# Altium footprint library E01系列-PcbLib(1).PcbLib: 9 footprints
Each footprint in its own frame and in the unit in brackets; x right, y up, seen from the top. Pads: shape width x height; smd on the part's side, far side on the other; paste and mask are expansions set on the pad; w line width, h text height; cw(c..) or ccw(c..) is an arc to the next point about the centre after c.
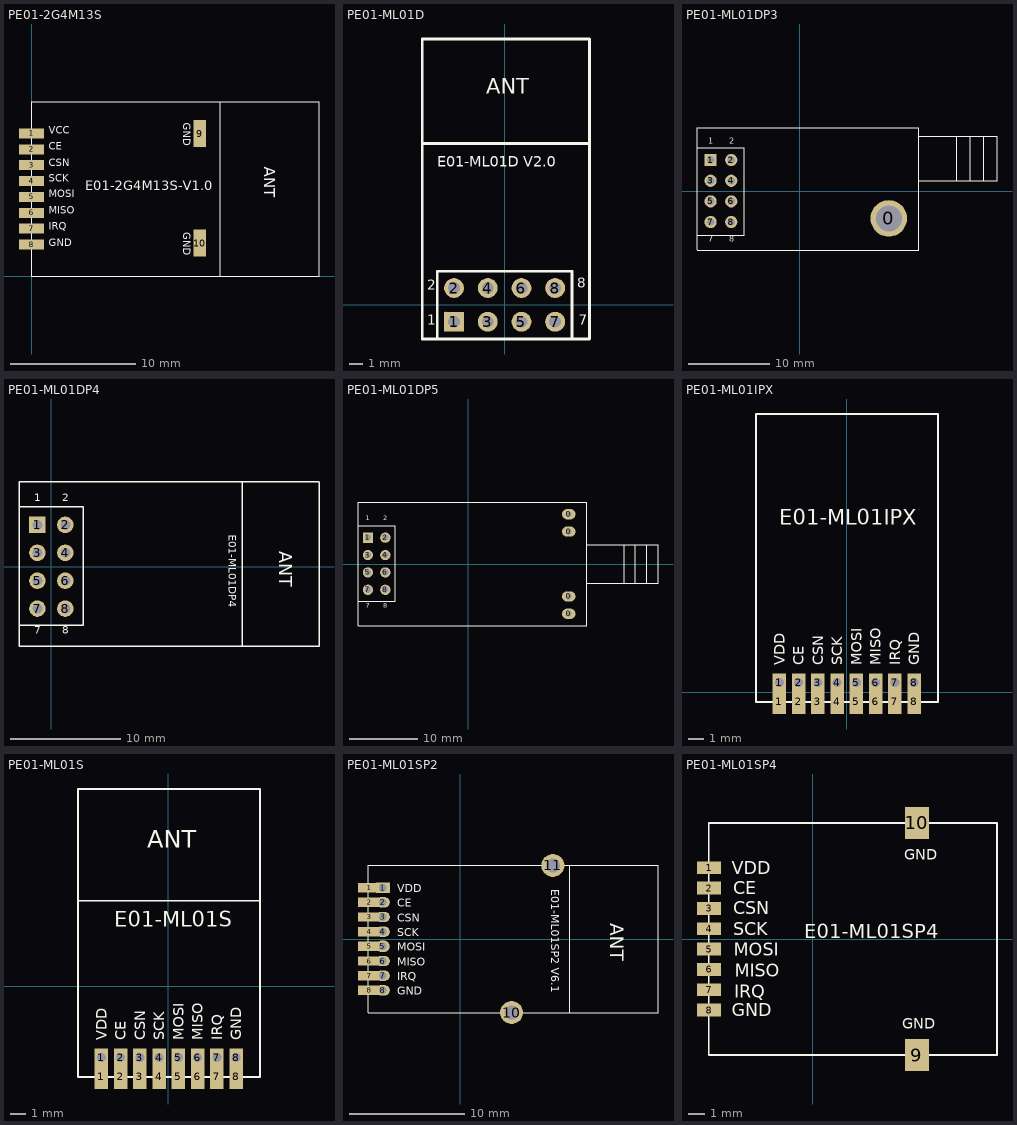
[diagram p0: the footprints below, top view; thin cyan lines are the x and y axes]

## PE01-2G4M13S [mm] "23*14mm-S"
pads (10):
  rect 2x0.8 smd: 1(0,11.445) 2(0,10.175) 3(0,8.905) 4(0,7.635) 5(0,6.365) 6(0,5.095) 7(0,3.825) 8(0,2.555)
  rect 1x2.15 smd: 9(13.462,11.43) 10(13.462,2.667)
Top Overlay:
  lines w0.1: 15.113,0 15.113,13.97 ; 0,0 0,14 23,14 23,0 0,0
  text "VCC" at 1.391,11.227 h1
  text "CE" at 1.391,9.927 h1
  text "CSN" at 1.391,8.627 h1
  text "SCK" at 1.397,7.366 h1
  text "MOSI" at 1.391,6.127 h1
  text "MISO" at 1.391,4.827 h1
  text "IRQ" at 1.391,3.527 h1
  text "GND" at 1.391,2.227 h1
  text "E01-2G4M13S-V1.0" at 4.318,6.604 h1.3
  text "ANT" at 18.288,8.763 h1.5
  text "GND" at 11.938,12.319 h1
  text "GND" at 11.938,3.556 h1

## PE01-ML01D [mm] "22.6mm*12.6mm-D"
pads (8):
  rect 1.5x1.5 hole 0.9: 1(-3.81,-1.27)
  round 1.5 hole 0.9: 2(-3.81,1.27) 3(-1.27,-1.27) 4(-1.27,1.27) 5(1.27,-1.27) 6(1.27,1.27) 7(3.81,-1.27) 8(3.81,1.27)
Top Layer:
  lines w0.254: -4.179,-1.27 ccw(c-5.07,-1.27) -4.44,-0.64 ccw(c-3.81,-0.01) -3.81,-0.901 ; -1.27,1.27 -1.15,1.39
Top Overlay:
  lines w0.2: -6.21,12.162 6.39,12.162 ; -6.21,-2.57 6.39,-2.57 6.39,20.037 -6.21,20.037 -6.21,-2.57 ; -5.08,-2.54 5.08,-2.54 5.08,2.54 -5.08,2.54 -5.08,-2.54
  text "ANT" at -1.397,15.494 h2
  text "E01-ML01D V2.0" at -5.08,10.414 h0.8
  text "1" at -5.842,-1.778 h1.27
  text "2" at -5.842,0.889 h1.27
  text "7" at 5.588,-1.778 h1.27
  text "8" at 5.461,1.016 h1.27

## PE01-ML01DP3 [mm] "27.3mm*15mm-D"
pads (9):
  round 4.5 hole 3.2: 0(10.958,-3.366)
  rect 1.5x1.5 hole 0.9: 1(-10.958,3.81)
  round 1.5 hole 0.9: 2(-8.418,3.81) 3(-10.958,1.27) 4(-8.418,1.27) 5(-10.958,-1.27) 6(-8.418,-1.27) 7(-10.958,-3.81) 8(-8.418,-3.81)
Bottom Layer:
  lines w0.5: -8.418,3.81 -8.356,3.81
Top Overlay:
  lines w0.127: -12.632,-7.246 -12.632,7.754 14.668,7.754 14.668,-7.246 ; -12.632,-5.468 -6.79,-5.468 -6.79,5.327 -12.632,5.327 ; -12.629,-7.254 14.668,-7.254 ; 14.668,1.263 24.268,1.263 24.268,6.724 14.673,6.724 ; 19.315,1.263 19.315,6.724 ; 20.966,1.263 20.966,6.724 ; 22.617,1.263 22.617,6.724
  text "1" at -11.235,5.581 h1.2
  text "2" at -8.695,5.581 h1.2
  text "7" at -11.235,-6.484 h1.2
  text "8" at -8.695,-6.484 h1.2

## PE01-ML01DP4 [mm] "27.3mm*15mm-D"
pads (8):
  rect 1.5x1.5 hole 0.9: 1(-1.27,3.81)
  round 1.5 hole 0.9: 2(1.27,3.81) 3(-1.27,1.27) 4(1.27,1.27) 5(-1.27,-1.27) 6(1.27,-1.27) 7(-1.27,-3.81) 8(1.27,-3.81)
Top Overlay:
  lines w0.127: -2.944,-7.246 -2.944,7.754 24.356,7.754 24.356,-7.246 ; -2.944,-5.341 2.898,-5.341 2.898,5.454 -2.944,5.454 ; -2.941,-7.254 24.356,-7.254 ; 17.371,-7.246 17.371,7.754
  text "8" at 0.993,-6.357 h1.2
  text "7" at -1.547,-6.357 h1.2
  text "2" at 0.993,5.708 h1.2
  text "1" at -1.547,5.708 h1.2
  text "ANT" at 20.32,1.397 h2
  text "E01-ML01DP4" at 16.129,2.921 h0.7

## PE01-ML01DP5 [mm] "33.4mm*18mm-D"
pads (12):
  oval 2x1.5 hole 0.85: 0(14.665,-7.27) 0(14.665,-4.73) 0(14.665,4.73) 0(14.665,7.27)
  rect 1.5x1.5 hole 0.9: 1(-14.665,3.85)
  round 1.5 hole 0.9: 2(-12.125,3.85) 3(-14.665,1.31) 4(-12.125,1.31) 5(-14.665,-1.23) 6(-12.125,-1.23) 7(-14.665,-3.77) 8(-12.125,-3.77)
Top Overlay:
  lines w0.127: -16.115,-5.444 -10.654,-5.444 -10.654,5.605 -16.115,5.605 ; 17.275,-2.777 27.7,-2.777 27.7,2.811 17.286,2.811 ; 22.747,-2.777 22.747,2.811 ; 24.398,-2.777 24.398,2.811 ; 26.049,-2.777 26.049,2.811 ; -16.115,-9 -16.115,9 17.275,9 17.275,-9 -16.115,-9
  text "1" at -14.972,6.113 h1.2
  text "2" at -12.432,6.113 h1.2
  text "7" at -14.972,-6.714 h1.2
  text "8" at -12.432,-6.714 h1.2

## PE01-ML01IPX [mm] "19mm*12mm*1.63mm-S"
pads (16):
  rect 0.9x1.6 smd: 1(-4.445,-0.635) 2(-3.175,-0.635) 3(-1.905,-0.635) 4(-0.635,-0.635) 5(0.635,-0.635) 6(1.905,-0.635) 7(3.175,-0.635) 8(4.445,-0.635)
  rect 0.9x1.2 hole 0.6: 1(-4.445,0.635) 2(-3.175,0.635) 3(-1.905,0.635) 4(-0.635,0.635) 5(0.635,0.635) 6(1.905,0.635) 7(3.175,0.635) 8(4.445,0.635)
Top Overlay:
  lines w0.127: -5.985,-0.635 -5.985,18.365 6.015,18.365 6.015,-0.635 -5.985,-0.635
  text "GND" at 4.791,1.784 h0.7
  text "MISO" at 2.251,1.784 h0.7
  text "MOSI" at 0.981,1.784 h0.7
  text "SCK" at -0.289,1.784 h0.7
  text "CSN" at -1.559,1.784 h0.7
  text "CE" at -2.829,1.784 h0.7
  text "VDD" at -4.099,1.784 h0.7
  text "IRQ" at 3.521,1.784 h0.7
  text "E01-ML01IPX" at -4.445,11.049 h1

## PE01-ML01S [mm] "19mm*12mm*1.63mm-S"
pads (16):
  rect 0.9x1.6 smd: 1(-4.41,-5.975) 2(-3.14,-5.975) 3(-1.87,-5.975) 4(-0.6,-5.975) 5(0.67,-5.975) 6(1.94,-5.975) 7(3.21,-5.975) 8(4.48,-5.975)
  rect 0.9x1.2 hole 0.6: 1(-4.41,-4.705) 2(-3.14,-4.705) 3(-1.87,-4.705) 4(-0.6,-4.705) 5(0.67,-4.705) 6(1.94,-4.705) 7(3.21,-4.705) 8(4.48,-4.705)
Top Overlay:
  lines w0.1: -5.95,5.659 6.05,5.659
  lines w0.127: -5.95,-5.975 -5.95,13.025 6.05,13.025 6.05,-5.975 -5.95,-5.975
  text "GND" at 4.826,-3.556 h0.7
  text "MISO" at 2.286,-3.556 h0.7
  text "MOSI" at 1.016,-3.556 h0.7
  text "SCK" at -0.254,-3.556 h0.7
  text "CSN" at -1.524,-3.556 h0.7
  text "CE" at -2.794,-3.556 h0.7
  text "VDD" at -4.064,-3.556 h0.7
  text "IRQ" at 3.556,-3.556 h0.7
  text "ANT" at -1.397,8.763 h2
  text "E01-ML01S" at -3.556,3.937 h1

## PE01-ML01SP2 [mm] "25.1mm*12.8mm*2.10mm-S"
pads (18):
  rect 2x0.8 smd: 1(-7.874,4.445) 2(-7.873,3.175) 3(-7.873,1.905) 4(-7.873,0.635) 5(-7.873,-0.635) 6(-7.873,-1.905) 7(-7.873,-3.175) 8(-7.873,-4.445)
  rect 1.2x0.9 hole 0.65: 1(-6.721,4.445)
  oval 1.2x0.9 hole 0.65: 2(-6.721,3.175) 3(-6.721,1.905) 4(-6.721,0.635) 6(-6.721,-1.905) 7(-6.721,-3.175) 8(-6.721,-4.445)
  oval 1.2x1 hole 0.65: 5(-6.721,-0.635)
  round 2 hole 1.2: 10(4.42,-6.365) 11(8,6.365)
Top Layer:
  lines w0.22: -6.73,-0.255 -6.73,-0.56 ccw(c-6.662,-0.56) -6.71,-0.608 ; -6.671,0.685 -6.721,0.635 cw(c-6.6,0.514) -6.6,0.685 ; -6.653,-0.567 -6.721,-0.635 ; -6.404,3.175 -6.721,3.175 -6.329,3.175 ; -6.327,-0.472 cw(c-6.721,-0.077) -6.721,-0.635 ; -6.721,-0.635 ccw(c-6.748,-0.608) -6.71,-0.608 ; -6.721,-0.635 ccw(c-6.748,-0.608) -6.71,-0.608
Bottom Layer:
  lines w0.6: -7.65,-4.445 -7.62,-4.475 -6.751,-4.475 -6.721,-4.445
Top Overlay:
  lines w0.1: 9.48,-6.365 9.48,6.365 ; -8,-6.365 17.1,-6.365 17.1,6.365 -8,6.365 -8,-6.365
  text "ANT" at 12.574,1.382 h2
  text "E01-ML01SP2 V6.1" at 7.874,4.318 h0.7
  text "VDD" at -5.46,4.049 h0.7
  text "CE" at -5.46,2.779 h0.7
  text "CSN" at -5.46,1.509 h0.7
  text "SCK" at -5.46,0.239 h0.7
  text "MOSI" at -5.46,-1.031 h0.7
  text "MISO" at -5.46,-2.301 h0.7
  text "IRQ" at -5.46,-3.571 h0.7
  text "GND" at -5.46,-4.841 h0.7

## PE01-ML01SP4 [mm] "18mm*14.5mm*2.4mm-S"
pads (10):
  rect 1.5x0.8 smd: 1(-6.497,4.453) 2(-6.497,3.183) 3(-6.497,1.913) 4(-6.497,0.643) 5(-6.497,-0.627) 6(-6.497,-1.897) 7(-6.497,-3.167) 8(-6.497,-4.437)
  rect 1.5x2 smd: 9(6.497,-7.25) 10(6.497,7.25)
Top Overlay:
  lines w0.1: -6.503,-7.25 11.497,-7.25 11.497,7.25 -6.503,7.25 -6.503,-7.25
  text "E01-ML01SP4" at -0.543,0.06 h0.9
  text "VDD" at -5.068,4.06 h0.8
  text "GND" at 5.689,4.942 h0.65
  text "CE" at -4.988,2.8 h0.8
  text "CSN" at -4.988,1.55 h0.8
  text "SCK" at -4.968,0.23 h0.8
  text "MOSI" at -4.948,-1.05 h0.8
  text "MISO" at -4.898,-2.35 h0.8
  text "IRQ" at -4.918,-3.66 h0.8
  text "GND" at -5.068,-4.84 h0.8
  text "GND" at 5.562,-5.599 h0.65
